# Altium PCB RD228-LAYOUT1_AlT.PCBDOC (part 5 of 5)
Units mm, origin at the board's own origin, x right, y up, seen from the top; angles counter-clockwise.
Board outline 130 x 73 mm, 4 copper layers (TOP, Mid-Layer 1, Mid-Layer 2, BOTTOM), stack 0.711 mm thick; 225 components, 171 nets, 818 pads, 538 vias.
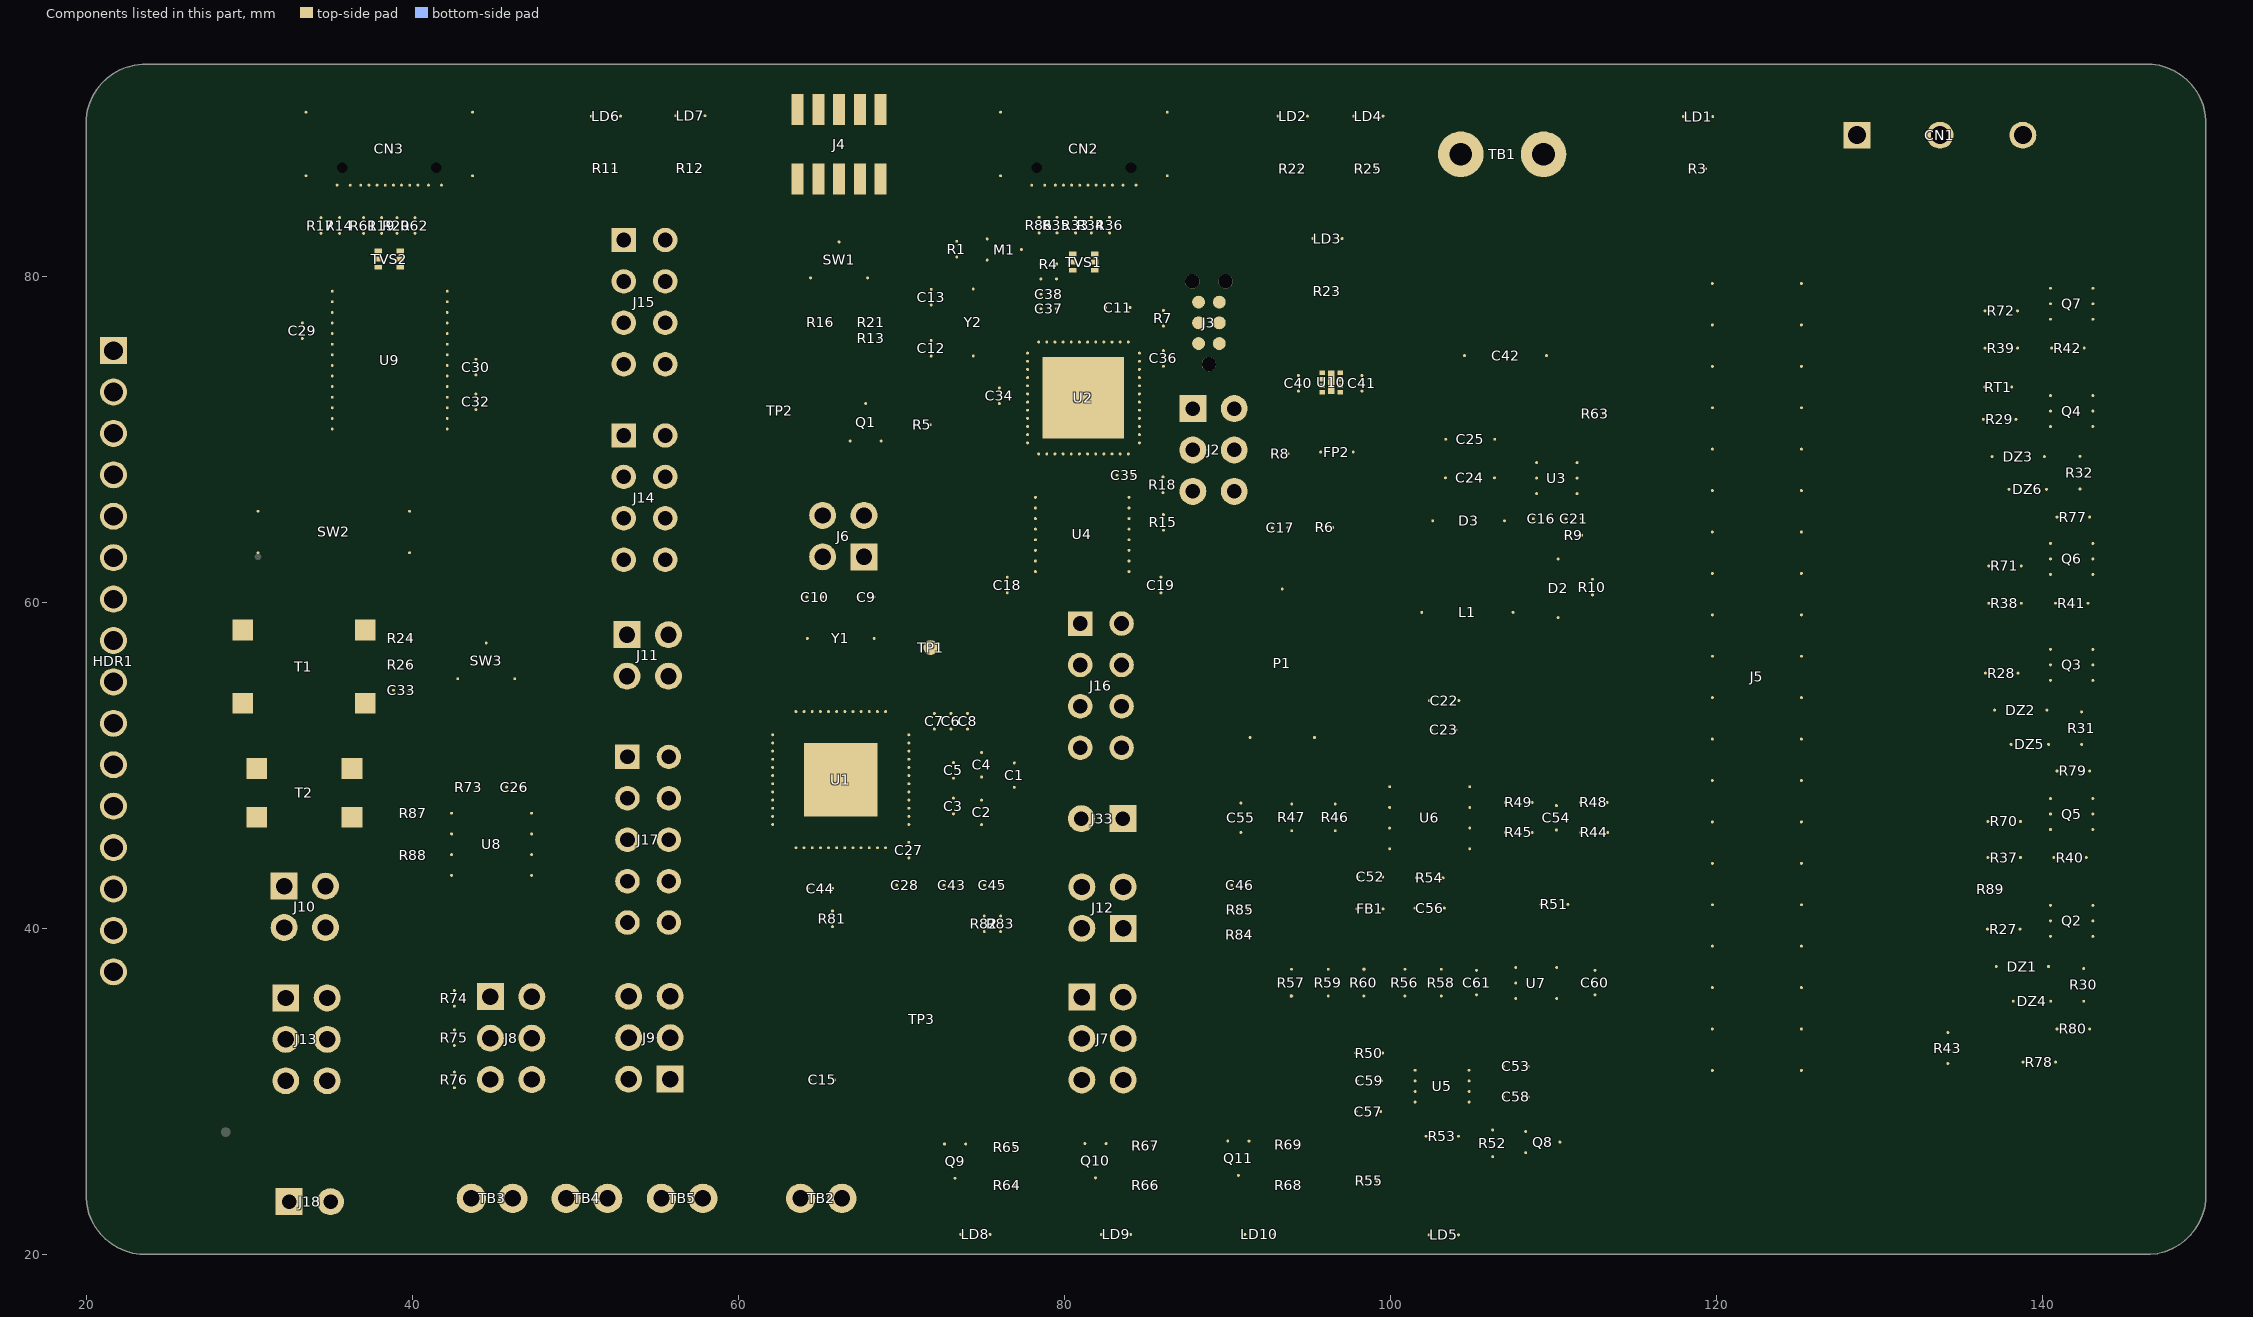
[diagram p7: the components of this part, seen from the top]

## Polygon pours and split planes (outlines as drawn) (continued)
no net on Top Overlay "TOPOVERLAY338" (solid, pour order 0): 165 vertices, not listed, extent 57.634,54.969 58.568,55.978
no net on Top Overlay "TOPOVERLAY337" (solid, pour order 0): 57.316,54.985 57.316,55.961 57.446,55.961 57.446,54.985
no net on Top Overlay "TOPOVERLAY336" (solid, pour order 0): 48 vertices, not listed, extent 58.498,81.756 58.857,82.737
no net on Top Overlay "TOPOVERLAY335" (solid, pour order 0): 165 vertices, not listed, extent 57.354,81.74 58.289,82.75
no net on Top Overlay "TOPOVERLAY334" (solid, pour order 0): 57.037,81.756 57.037,82.733 57.167,82.733 57.167,81.756
no net on Top Overlay "TOPOVERLAY333" (solid, pour order 0): 58.791,79.216 58.791,79.45 58.367,79.45 58.367,79.559 58.813,80.193 58.911,80.193 58.911,79.559 59.042,79.559 59.042,79.45 58.911,79.45 58.911,79.216
no net on Top Overlay "TOPOVERLAY332" (solid, pour order 0): 165 vertices, not listed, extent 57.354,79.2 58.289,80.21
no net on Top Overlay "TOPOVERLAY331" (solid, pour order 0): 57.037,79.216 57.037,80.193 57.167,80.193 57.167,79.216
no net on Top Overlay "TOPOVERLAY330" (solid, pour order 0): 165 vertices, not listed, extent 57.354,76.66 58.289,77.67
no net on Top Overlay "TOPOVERLAY329" (solid, pour order 0): 203 vertices, not listed, extent 58.405,76.66 59.048,77.657
no net on Top Overlay "TOPOVERLAY328" (solid, pour order 0): 57.037,76.676 57.037,77.653 57.167,77.653 57.167,76.676
no net on Top Overlay "TOPOVERLAY327" (solid, pour order 0): 48 vertices, not listed, extent 59.256,74.035 59.616,75.015
no net on Top Overlay "TOPOVERLAY326" (solid, pour order 0): 48 vertices, not listed, extent 58.498,74.035 58.857,75.015
no net on Top Overlay "TOPOVERLAY325" (solid, pour order 0): 165 vertices, not listed, extent 57.354,74.019 58.289,75.028
no net on Top Overlay "TOPOVERLAY324" (solid, pour order 0): 57.037,74.035 57.037,75.011 57.167,75.011 57.167,74.035
no net on Top Overlay "TOPOVERLAY323" (solid, pour order 0): 57.037,69.768 57.037,70.744 57.167,70.744 57.167,69.768
no net on Top Overlay "TOPOVERLAY322" (solid, pour order 0): 165 vertices, not listed, extent 57.354,69.751 58.289,70.761
no net on Top Overlay "TOPOVERLAY321" (solid, pour order 0): 152 vertices, not listed, extent 58.406,69.751 59.042,70.748
no net on Top Overlay "TOPOVERLAY320" (solid, pour order 0): 312 vertices, not listed, extent 58.407,67.186 59.046,68.182
no net on Top Overlay "TOPOVERLAY319" (solid, pour order 0): 165 vertices, not listed, extent 57.354,67.186 58.289,68.196
no net on Top Overlay "TOPOVERLAY318" (solid, pour order 0): 57.037,67.202 57.037,68.179 57.167,68.179 57.167,67.202
no net on Top Overlay "TOPOVERLAY317" (solid, pour order 0): 93 vertices, not listed, extent 58.414,64.688 59.046,65.652
no net on Top Overlay "TOPOVERLAY316" (solid, pour order 0): 165 vertices, not listed, extent 57.354,64.671 58.289,65.681
no net on Top Overlay "TOPOVERLAY315" (solid, pour order 0): 57.037,64.688 57.037,65.664 57.167,65.664 57.167,64.688
no net on Top Overlay "TOPOVERLAY314" (solid, pour order 0): 48 vertices, not listed, extent 58.498,62.148 58.857,63.128
no net on Top Overlay "TOPOVERLAY313" (solid, pour order 0): 165 vertices, not listed, extent 57.354,62.131 58.289,63.141
no net on Top Overlay "TOPOVERLAY312" (solid, pour order 0): 152 vertices, not listed, extent 59.164,62.131 59.8,63.128
no net on Top Overlay "TOPOVERLAY311" (solid, pour order 0): 57.037,62.148 57.037,63.124 57.167,63.124 57.167,62.148
no net on Top Overlay "TOPOVERLAY310" (solid, pour order 0): 295 vertices, not listed, extent 56.681,26.927 57.584,27.937
no net on Top Overlay "TOPOVERLAY309" (solid, pour order 0): 57.774,26.943 57.774,27.92 57.906,27.92 58.42,27.153 58.42,27.92 58.544,27.92 58.544,26.943 58.41,26.943 57.898,27.709 57.898,26.943
no net on Top Overlay "TOPOVERLAY308" (solid, pour order 0): 100 vertices, not listed, extent 58.76,26.943 59.568,27.92
no net on Top Overlay "TOPOVERLAY307" (solid, pour order 0): 50 vertices, not listed, extent 57.007,87.649 57.902,88.626
no net on Top Overlay "TOPOVERLAY306" (solid, pour order 0): 56.521,87.649 56.521,88.51 56.199,88.51 56.199,88.626 56.973,88.626 56.973,88.51 56.65,88.51 56.65,87.649
no net on Top Overlay "TOPOVERLAY305" (solid, pour order 0): 216 vertices, not listed, extent 57.596,85.135 58.241,86.115
no net on Top Overlay "TOPOVERLAY304" (solid, pour order 0): 119 vertices, not listed, extent 55.919,85.135 56.778,86.111
no net on Top Overlay "TOPOVERLAY303" (solid, pour order 0): 48 vertices, not listed, extent 56.945,85.135 57.304,86.115
no net on Top Overlay "TOPOVERLAY302" (solid, pour order 0): 53.975,27.101 53.975,27.369 53.71,27.369 53.71,27.48 53.975,27.48 53.975,27.746 54.089,27.746 54.089,27.48 54.355,27.48 54.355,27.369 54.089,27.369 54.089,27.101
no net on Top Overlay "TOPOVERLAY301" (solid, pour order 0): 31 vertices, not listed, extent 55.194,26.943 56.087,27.92
no net on Top Overlay "TOPOVERLAY300" (solid, pour order 0): 200 vertices, not listed, extent 54.486,26.927 55.134,27.907
no net on Top Overlay "TOPOVERLAY299" (solid, pour order 0): 110 vertices, not listed, extent 53.484,59.591 54.021,60.584
no net on Top Overlay "TOPOVERLAY298" (solid, pour order 0): 48 vertices, not listed, extent 55.034,59.608 55.393,60.588
no net on Top Overlay "TOPOVERLAY297" (solid, pour order 0): 48 vertices, not listed, extent 54.275,59.608 54.635,60.588
no net on Top Overlay "TOPOVERLAY296" (solid, pour order 0): 110 vertices, not listed, extent 53.408,51.895 53.945,52.888
no net on Top Overlay "TOPOVERLAY295" (solid, pour order 0): 93 vertices, not listed, extent 54.874,51.911 55.505,52.875
no net on Top Overlay "TOPOVERLAY294" (solid, pour order 0): 48 vertices, not listed, extent 54.199,51.911 54.558,52.892
no net on Top Overlay "TOPOVERLAY293" (solid, pour order 0): 110 vertices, not listed, extent 53.281,37.519 53.818,38.511
no net on Top Overlay "TOPOVERLAY292" (solid, pour order 0): 241 vertices, not listed, extent 53.98,37.519 54.622,38.515
no net on Top Overlay "TOPOVERLAY291" (solid, pour order 0): 110 vertices, not listed, extent 53.179,83.594 53.716,84.587
no net on Top Overlay "TOPOVERLAY290" (solid, pour order 0): 200 vertices, not listed, extent 54.636,83.594 55.284,84.575
no net on Top Overlay "TOPOVERLAY289" (solid, pour order 0): 48 vertices, not listed, extent 53.971,83.611 54.33,84.591
no net on Top Overlay "TOPOVERLAY288" (solid, pour order 0): 110 vertices, not listed, extent 53.154,71.606 53.691,72.598
no net on Top Overlay "TOPOVERLAY287" (solid, pour order 0): 48 vertices, not listed, extent 53.945,71.622 54.304,72.602
no net on Top Overlay "TOPOVERLAY286" (solid, pour order 0): 54.996,71.622 54.996,71.855 54.572,71.855 54.572,71.965 55.018,72.598 55.116,72.598 55.116,71.965 55.247,71.965 55.247,71.855 55.116,71.855 55.116,71.622
no net on Top Overlay "TOPOVERLAY285" (solid, pour order 0): 50 vertices, not listed, extent 51.864,87.598 52.759,88.575
no net on Top Overlay "TOPOVERLAY284" (solid, pour order 0): 119 vertices, not listed, extent 50.981,87.598 51.839,88.575
no net on Top Overlay "TOPOVERLAY283" (solid, pour order 0): 48 vertices, not listed, extent 52.598,85.084 52.957,86.064
no net on Top Overlay "TOPOVERLAY282" (solid, pour order 0): 119 vertices, not listed, extent 50.814,85.084 51.672,86.06
no net on Top Overlay "TOPOVERLAY281" (solid, pour order 0): 48 vertices, not listed, extent 51.84,85.084 52.199,86.064
no net on Top Overlay "TOPOVERLAY280" (solid, pour order 0): 50.763,26.943 50.763,27.92 50.893,27.92 50.893,27.519 51.4,27.519 51.4,27.92 51.529,27.92 51.529,26.943 51.4,26.943 51.4,27.403 50.893,27.403 50.893,26.943
no net on Top Overlay "TOPOVERLAY279" (solid, pour order 0): 51.681,27.237 51.681,27.358 52.05,27.358 52.05,27.237
no net on Top Overlay "TOPOVERLAY278" (solid, pour order 0): 96 vertices, not listed, extent 52.109,26.943 53.366,27.92
no net on Top Overlay "TOPOVERLAY277" (solid, pour order 0): 371 vertices, not listed, extent 50.864,42.37 51.64,43.38
no net on Top Overlay "TOPOVERLAY276" (solid, pour order 0): 274 vertices, not listed, extent 49.885,42.37 50.747,43.38
no net on Top Overlay "TOPOVERLAY275" (solid, pour order 0): 371 vertices, not listed, extent 49.55,47.45 50.327,48.46
no net on Top Overlay "TOPOVERLAY274" (solid, pour order 0): 100 vertices, not listed, extent 50.503,47.466 51.311,48.443
no net on Top Overlay "TOPOVERLAY273" (solid, pour order 0): 51.511,47.466 51.511,48.443 51.64,48.443 51.64,47.466
no net on Top Overlay "TOPOVERLAY272" (solid, pour order 0): 96 vertices, not listed, extent 49.517,39.846 50.773,40.823
no net on Top Overlay "TOPOVERLAY271" (solid, pour order 0): 75 vertices, not listed, extent 50.893,39.846 51.639,40.823
no net on Top Overlay "TOPOVERLAY270" (solid, pour order 0): 49.315,30.271 49.315,31.247 49.445,31.247 49.445,30.846 49.952,30.846 49.952,31.247 50.081,31.247 50.081,30.271 49.952,30.271 49.952,30.731 49.445,30.731 49.445,30.271
no net on Top Overlay "TOPOVERLAY269" (solid, pour order 0): 50.234,30.564 50.234,30.685 50.602,30.685 50.602,30.564
no net on Top Overlay "TOPOVERLAY268" (solid, pour order 0): 148 vertices, not listed, extent 50.753,30.254 51.521,31.247
no net on Top Overlay "TOPOVERLAY267" (solid, pour order 0): 49.188,32.633 49.188,33.609 49.318,33.609 49.318,33.208 49.825,33.208 49.825,33.609 49.954,33.609 49.954,32.633 49.825,32.633 49.825,33.093 49.318,33.093 49.318,32.633
no net on Top Overlay "TOPOVERLAY266" (solid, pour order 0): 50.107,32.926 50.107,33.047 50.475,33.047 50.475,32.926
no net on Top Overlay "TOPOVERLAY265" (solid, pour order 0): 31 vertices, not listed, extent 50.524,32.633 51.417,33.609
no net on Top Overlay "TOPOVERLAY264" (solid, pour order 0): 48.985,35.249 48.985,36.225 49.115,36.225 49.115,35.824 49.622,35.824 49.622,36.225 49.751,36.225 49.751,35.249 49.622,35.249 49.622,35.709 49.115,35.709 49.115,35.249
no net on Top Overlay "TOPOVERLAY263" (solid, pour order 0): 49.903,35.542 49.903,35.663 50.272,35.663 50.272,35.542
no net on Top Overlay "TOPOVERLAY262" (solid, pour order 0): 96 vertices, not listed, extent 50.331,35.249 51.588,36.225
no net on Top Overlay "TOPOVERLAY261" (solid, pour order 0): 371 vertices, not listed, extent 48.901,44.91 49.677,45.92
no net on Top Overlay "TOPOVERLAY260" (solid, pour order 0): 274 vertices, not listed, extent 49.816,44.91 50.679,45.92
no net on Top Overlay "TOPOVERLAY259" (solid, pour order 0): 50.833,44.926 50.833,45.903 50.963,45.903 50.963,45.419 51.447,45.903 51.622,45.903 51.212,45.507 51.64,44.926 51.469,44.926 51.122,45.419 50.963,45.265 50.963,44.926
no net on Top Overlay "TOPOVERLAY258" (solid, pour order 0): 371 vertices, not listed, extent 48.807,49.99 49.584,51
no net on Top Overlay "TOPOVERLAY257" (solid, pour order 0): 165 vertices, not listed, extent 50.706,49.99 51.64,51
no net on Top Overlay "TOPOVERLAY256" (solid, pour order 0): 100 vertices, not listed, extent 49.76,50.006 50.568,50.983
no net on Top Overlay "TOPOVERLAY255" (solid, pour order 0): 47.995,26.918 47.995,27.894 48.124,27.894 48.124,27.493 48.631,27.493 48.631,27.894 48.76,27.894 48.76,26.918 48.631,26.918 48.631,27.378 48.124,27.378 48.124,26.918
no net on Top Overlay "TOPOVERLAY254" (solid, pour order 0): 48.913,27.211 48.913,27.332 49.282,27.332 49.282,27.211
no net on Top Overlay "TOPOVERLAY253" (solid, pour order 0): 31 vertices, not listed, extent 49.33,26.918 50.224,27.894
no net on Top Overlay "TOPOVERLAY252" (solid, pour order 0): 119 vertices, not listed, extent 49.235,56.306 50.093,57.282
no net on Top Overlay "TOPOVERLAY251" (solid, pour order 0): 100 vertices, not listed, extent 47.868,56.306 48.675,57.282
no net on Top Overlay "TOPOVERLAY250" (solid, pour order 0): 48.875,56.306 48.875,57.282 49.005,57.282 49.005,56.306
no net on Top Overlay "TOPOVERLAY249" (solid, pour order 0): 50 vertices, not listed, extent 48.269,77.464 49.164,78.44
no net on Top Overlay "TOPOVERLAY248" (solid, pour order 0): 47.783,77.464 47.783,78.325 47.461,78.325 47.461,78.44 48.236,78.44 48.236,78.325 47.913,78.325 47.913,77.464
no net on Top Overlay "TOPOVERLAY247" (solid, pour order 0): 50 vertices, not listed, extent 47.989,65.373 48.884,66.35
no net on Top Overlay "TOPOVERLAY246" (solid, pour order 0): 119 vertices, not listed, extent 47.106,65.373 47.964,66.35
no net on Top Overlay "TOPOVERLAY245" (solid, pour order 0): 148 vertices, not listed, extent 46.742,78.845 47.51,79.837
no net on Top Overlay "TOPOVERLAY244" (solid, pour order 0): 47.618,78.861 47.991,79.837 48.132,79.837 48.531,78.861 48.384,78.861 48.271,79.156 47.861,79.156 47.754,78.861
no net on Top Overlay "TOPOVERLAY243" (solid, pour order 0): 119 vertices, not listed, extent 48.636,78.861 49.495,79.837
no net on Top Overlay "TOPOVERLAY242" (solid, pour order 0): 49.867,78.861 49.867,79.722 49.545,79.722 49.545,79.837 50.319,79.837 50.319,79.722 49.996,79.722 49.996,78.861
no net on Top Overlay "TOPOVERLAY241" (solid, pour order 0): 148 vertices, not listed, extent 46.386,66.754 47.154,67.747
no net on Top Overlay "TOPOVERLAY240" (solid, pour order 0): 47.263,66.77 47.636,67.747 47.776,67.747 48.175,66.77 48.028,66.77 47.915,67.066 47.505,67.066 47.399,66.77
no net on Top Overlay "TOPOVERLAY239" (solid, pour order 0): 119 vertices, not listed, extent 48.281,66.77 49.139,67.747
no net on Top Overlay "TOPOVERLAY238" (solid, pour order 0): 49.511,66.77 49.511,67.632 49.189,67.632 49.189,67.747 49.964,67.747 49.964,67.632 49.641,67.632 49.641,66.77
no net on Top Overlay "TOPOVERLAY237" (solid, pour order 0): 110 vertices, not listed, extent 45.376,37.57 45.913,38.562
no net on Top Overlay "TOPOVERLAY236" (solid, pour order 0): 203 vertices, not listed, extent 46.074,37.57 46.717,38.566
no net on Top Overlay "TOPOVERLAY235" (solid, pour order 0): 274 vertices, not listed, extent 45.15,87.551 46.013,88.56
no net on Top Overlay "TOPOVERLAY234" (solid, pour order 0): 312 vertices, not listed, extent 47.109,87.551 47.748,88.547
no net on Top Overlay "TOPOVERLAY233" (solid, pour order 0): 46.171,87.567 46.171,88.543 46.303,88.543 46.817,87.776 46.817,88.543 46.941,88.543 46.941,87.567 46.807,87.567 46.295,88.333 46.295,87.567
no net on Top Overlay "TOPOVERLAY232" (solid, pour order 0): 220 vertices, not listed, extent 46.826,49.228 47.471,50.225
no net on Top Overlay "TOPOVERLAY231" (solid, pour order 0): 274 vertices, not listed, extent 45.099,49.228 45.962,50.238
no net on Top Overlay "TOPOVERLAY230" (solid, pour order 0): 216 vertices, not listed, extent 46.057,49.244 46.702,50.225
no net on Top Overlay "TOPOVERLAY229" (solid, pour order 0): 45.074,26.918 45.074,27.894 45.203,27.894 45.203,27.493 45.71,27.493 45.71,27.894 45.839,27.894 45.839,26.918 45.71,26.918 45.71,27.378 45.203,27.378 45.203,26.918
no net on Top Overlay "TOPOVERLAY228" (solid, pour order 0): 45.992,27.211 45.992,27.332 46.361,27.332 46.361,27.211
no net on Top Overlay "TOPOVERLAY227" (solid, pour order 0): 148 vertices, not listed, extent 46.511,26.902 47.279,27.894
no net on Top Overlay "TOPOVERLAY226" (solid, pour order 0): 274 vertices, not listed, extent 44.489,71.783 45.352,72.793
no net on Top Overlay "TOPOVERLAY225" (solid, pour order 0): 312 vertices, not listed, extent 45.464,71.783 46.103,72.78
no net on Top Overlay "TOPOVERLAY224" (solid, pour order 0): 216 vertices, not listed, extent 46.206,71.8 46.851,72.78
no net on Top Overlay "TOPOVERLAY223" (solid, pour order 0): 274 vertices, not listed, extent 44.464,73.917 45.327,74.927
no net on Top Overlay "TOPOVERLAY222" (solid, pour order 0): 312 vertices, not listed, extent 45.438,73.917 46.078,74.913
no net on Top Overlay "TOPOVERLAY221" (solid, pour order 0): 151 vertices, not listed, extent 46.196,73.917 46.832,74.913
no net on Top Overlay "TOPOVERLAY220" (solid, pour order 0): 148 vertices, not listed, extent 44.235,41.329 45.003,42.321
no net on Top Overlay "TOPOVERLAY219" (solid, pour order 0): 203 vertices, not listed, extent 45.168,41.329 45.811,42.325
no net on Top Overlay "TOPOVERLAY218" (solid, pour order 0): 371 vertices, not listed, extent 43.092,58.474 43.869,59.484
no net on Top Overlay "TOPOVERLAY217" (solid, pour order 0): 312 vertices, not listed, extent 45.285,58.474 45.924,59.47
no net on Top Overlay "TOPOVERLAY216" (solid, pour order 0): 96 vertices, not listed, extent 43.956,58.49 45.213,59.466
no net on Top Overlay "TOPOVERLAY215" (solid, pour order 0): 312 vertices, not listed, extent 43.947,49.228 44.586,50.225
no net on Top Overlay "TOPOVERLAY214" (solid, pour order 0): 119 vertices, not listed, extent 42.254,49.244 43.112,50.221
no net on Top Overlay "TOPOVERLAY213" (solid, pour order 0): 94 vertices, not listed, extent 43.196,49.244 43.828,50.208
no net on Top Overlay "TOPOVERLAY212" (solid, pour order 0): 42.393,27.076 42.393,27.344 42.127,27.344 42.127,27.455 42.393,27.455 42.393,27.721 42.506,27.721 42.506,27.455 42.772,27.455 42.772,27.344 42.506,27.344 42.506,27.076
no net on Top Overlay "TOPOVERLAY211" (solid, pour order 0): 31 vertices, not listed, extent 43.611,26.918 44.505,27.894
no net on Top Overlay "TOPOVERLAY210" (solid, pour order 0): 200 vertices, not listed, extent 42.904,26.902 43.551,27.882
no net on Top Overlay "TOPOVERLAY209" (solid, pour order 0): 42 vertices, not listed, extent 41.162,65.119 42.096,66.096
no net on Top Overlay "TOPOVERLAY208" (solid, pour order 0): 151 vertices, not listed, extent 43.239,65.103 43.875,66.1
no net on Top Overlay "TOPOVERLAY207" (solid, pour order 0): 100 vertices, not listed, extent 42.302,65.119 43.11,66.096
no net on Top Overlay "TOPOVERLAY206" (solid, pour order 0): 42 vertices, not listed, extent 41.162,62.554 42.096,63.53
no net on Top Overlay "TOPOVERLAY205" (solid, pour order 0): 100 vertices, not listed, extent 42.302,62.554 43.11,63.53
no net on Top Overlay "TOPOVERLAY204" (solid, pour order 0): 48 vertices, not listed, extent 43.331,62.554 43.69,63.534
no net on Top Overlay "TOPOVERLAY203" (solid, pour order 0): 220 vertices, not listed, extent 41.684,82.604 42.329,83.6
no net on Top Overlay "TOPOVERLAY202" (solid, pour order 0): 119 vertices, not listed, extent 40.756,82.62 41.614,83.596
no net on Top Overlay "TOPOVERLAY201" (solid, pour order 0): 216 vertices, not listed, extent 42.432,82.62 43.077,83.6
no net on Top Overlay "TOPOVERLAY200" (solid, pour order 0): 30 vertices, not listed, extent 40.537,80.563 41.43,81.539
no net on Top Overlay "TOPOVERLAY199" (solid, pour order 0): 371 vertices, not listed, extent 41.502,80.546 42.279,81.556
no net on Top Overlay "TOPOVERLAY198" (solid, pour order 0): 40.051,80.563 40.051,81.424 39.729,81.424 39.729,81.539 40.503,81.539 40.503,81.424 40.18,81.424 40.18,80.563
no net on Top Overlay "TOPOVERLAY197" (solid, pour order 0): 216 vertices, not listed, extent 42.391,80.563 43.036,81.543
no net on Top Overlay "TOPOVERLAY196" (solid, pour order 0): 41.765,35.147 41.765,35.381 41.341,35.381 41.341,35.49 41.787,36.124 41.885,36.124 41.885,35.49 42.017,35.49 42.017,35.381 41.885,35.381 41.885,35.147
no net on Top Overlay "TOPOVERLAY195" (solid, pour order 0): 119 vertices, not listed, extent 39.689,35.147 40.547,36.124
no net on Top Overlay "TOPOVERLAY194" (solid, pour order 0): 94 vertices, not listed, extent 40.631,35.147 41.262,36.111
no net on Top Overlay "TOPOVERLAY193" (solid, pour order 0): 220 vertices, not listed, extent 41.354,30.178 41.999,31.175
no net on Top Overlay "TOPOVERLAY192" (solid, pour order 0): 119 vertices, not listed, extent 39.667,30.194 40.526,31.171
no net on Top Overlay "TOPOVERLAY191" (solid, pour order 0): 94 vertices, not listed, extent 40.61,30.194 41.241,31.158
no net on Top Overlay "TOPOVERLAY190" (solid, pour order 0): 200 vertices, not listed, extent 41.304,32.769 41.952,33.749
no net on Top Overlay "TOPOVERLAY189" (solid, pour order 0): 119 vertices, not listed, extent 39.613,32.785 40.471,33.762
no net on Top Overlay "TOPOVERLAY188" (solid, pour order 0): 94 vertices, not listed, extent 40.555,32.785 41.186,33.749
no net on Top Overlay "TOPOVERLAY187" (solid, pour order 0): 203 vertices, not listed, extent 39.758,47.577 40.401,48.574
no net on Top Overlay "TOPOVERLAY186" (solid, pour order 0): 119 vertices, not listed, extent 38.825,47.593 39.683,48.57
no net on Top Overlay "TOPOVERLAY185" (solid, pour order 0): 94 vertices, not listed, extent 40.525,47.593 41.157,48.557
no net on Top Overlay "TOPOVERLAY184" (solid, pour order 0): 203 vertices, not listed, extent 39.758,45.012 40.401,46.008
no net on Top Overlay "TOPOVERLAY183" (solid, pour order 0): 203 vertices, not listed, extent 40.516,45.012 41.159,46.008
no net on Top Overlay "TOPOVERLAY182" (solid, pour order 0): 119 vertices, not listed, extent 38.825,45.028 39.683,46.004
no net on Top Overlay "TOPOVERLAY181" (solid, pour order 0): 40.216,58.439 40.216,58.673 39.792,58.673 39.792,58.782 40.238,59.416 40.336,59.416 40.336,58.782 40.467,58.782 40.467,58.673 40.336,58.673 40.336,58.439
no net on Top Overlay "TOPOVERLAY180" (solid, pour order 0): 119 vertices, not listed, extent 38.139,58.439 38.998,59.416
no net on Top Overlay "TOPOVERLAY179" (solid, pour order 0): 216 vertices, not listed, extent 39.058,58.439 39.703,59.419
no net on Top Overlay "TOPOVERLAY178" (solid, pour order 0): 274 vertices, not listed, extent 38.089,53.038 38.951,54.048
no net on Top Overlay "TOPOVERLAY177" (solid, pour order 0): 312 vertices, not listed, extent 39.821,53.038 40.46,54.035
no net on Top Overlay "TOPOVERLAY176" (solid, pour order 0): 312 vertices, not listed, extent 39.063,53.038 39.702,54.035
no net on Top Overlay "TOPOVERLAY175" (solid, pour order 0): 100 vertices, not listed, extent 21.035,77.134 21.843,78.11
no net on Top Overlay "TOPOVERLAY174" (solid, pour order 0): 20.055,77.134 20.055,78.11 20.184,78.11 20.184,77.709 20.691,77.709 20.691,78.11 20.82,78.11 20.82,77.134 20.691,77.134 20.691,77.594 20.184,77.594 20.184,77.134
no net on Top Overlay "TOPOVERLAY173" (solid, pour order 0): 48 vertices, not listed, extent 23.048,77.134 23.407,78.114
no net on Top Overlay "TOPOVERLAY172" (solid, pour order 0): 119 vertices, not listed, extent 22.023,77.134 22.881,78.11
no net on Top Overlay "TOPOVERLAY171" (solid, pour order 0): 94 vertices, not listed, extent 37.967,35.224 38.599,36.188
no net on Top Overlay "TOPOVERLAY170" (solid, pour order 0): 165 vertices, not listed, extent 36.907,35.207 37.842,36.217
no net on Top Overlay "TOPOVERLAY169" (solid, pour order 0): 36.59,35.224 36.59,36.2 36.72,36.2 36.72,35.224
no net on Top Overlay "TOPOVERLAY168" (solid, pour order 0): 165 vertices, not listed, extent 36.907,32.617 37.842,33.626
no net on Top Overlay "TOPOVERLAY167" (solid, pour order 0): 203 vertices, not listed, extent 37.958,32.617 38.601,33.613
no net on Top Overlay "TOPOVERLAY166" (solid, pour order 0): 36.59,32.633 36.59,33.609 36.72,33.609 36.72,32.633
no net on Top Overlay "TOPOVERLAY165" (solid, pour order 0): 241 vertices, not listed, extent 37.959,30.127 38.601,31.124
no net on Top Overlay "TOPOVERLAY164" (solid, pour order 0): 165 vertices, not listed, extent 36.907,30.127 37.842,31.137
no net on Top Overlay "TOPOVERLAY163" (solid, pour order 0): 36.59,30.144 36.59,31.12 36.72,31.12 36.72,30.144
no net on Top Overlay "TOPOVERLAY162" (solid, pour order 0): 241 vertices, not listed, extent 37.781,39.652 38.423,40.649
no net on Top Overlay "TOPOVERLAY161" (solid, pour order 0): 165 vertices, not listed, extent 36.729,39.652 37.664,40.662
no net on Top Overlay "TOPOVERLAY160" (solid, pour order 0): 36.412,39.669 36.412,40.645 36.542,40.645 36.542,39.669
no net on Top Overlay "TOPOVERLAY159" (solid, pour order 0): 94 vertices, not listed, extent 37.757,42.056 38.388,43.02
no net on Top Overlay "TOPOVERLAY158" (solid, pour order 0): 165 vertices, not listed, extent 36.696,42.04 37.631,43.05
no net on Top Overlay "TOPOVERLAY157" (solid, pour order 0): 36.379,42.056 36.379,43.033 36.509,43.033 36.509,42.056
no net on Top Overlay "TOPOVERLAY156" (solid, pour order 0): 148 vertices, not listed, extent 34.38,79.988 35.148,80.98
no net on Top Overlay "TOPOVERLAY155" (solid, pour order 0): 241 vertices, not listed, extent 35.314,79.988 35.956,80.984
no net on Top Overlay "TOPOVERLAY154" (solid, pour order 0): 295 vertices, not listed, extent 33.974,24.92 34.877,25.93
no net on Top Overlay "TOPOVERLAY153" (solid, pour order 0): 35.066,24.937 35.066,25.913 35.199,25.913 35.712,25.146 35.712,25.913 35.836,25.913 35.836,24.937 35.703,24.937 35.19,25.702 35.19,24.937
no net on Top Overlay "TOPOVERLAY152" (solid, pour order 0): 100 vertices, not listed, extent 36.052,24.937 36.86,25.913
no net on Top Overlay "TOPOVERLAY151" (solid, pour order 0): 371 vertices, not listed, extent 33.821,67.542 34.598,68.551
no net on Top Overlay "TOPOVERLAY150" (solid, pour order 0): 96 vertices, not listed, extent 34.685,67.558 35.942,68.534
no net on Top Overlay "TOPOVERLAY149" (solid, pour order 0): 216 vertices, not listed, extent 35.998,67.558 36.643,68.538
no net on Top Overlay "TOPOVERLAY148" (solid, pour order 0): 23.594,75.113 23.594,75.38 23.329,75.38 23.329,75.492 23.594,75.492 23.594,75.757 23.708,75.757 23.708,75.492 23.973,75.492 23.973,75.38 23.708,75.38 23.708,75.113
no net on Top Overlay "TOPOVERLAY147" (solid, pour order 0): 30 vertices, not listed, extent 24.813,74.954 25.706,75.931
no net on Top Overlay "TOPOVERLAY146" (solid, pour order 0): 200 vertices, not listed, extent 24.105,74.938 24.753,75.918
no net on Top Overlay "TOPOVERLAY145" (solid, pour order 0): 23.594,72.573 23.594,72.84 23.329,72.84 23.329,72.952 23.594,72.952 23.594,73.217 23.708,73.217 23.708,72.952 23.973,72.952 23.973,72.84 23.708,72.84 23.708,72.573
no net on Top Overlay "TOPOVERLAY144" (solid, pour order 0): 30 vertices, not listed, extent 24.813,72.414 25.706,73.391
no net on Top Overlay "TOPOVERLAY143" (solid, pour order 0): 200 vertices, not listed, extent 24.105,72.398 24.753,73.378
no net on Top Overlay "TOPOVERLAY142" (solid, pour order 0): 23.329,69.874 23.329,70.851 23.458,70.851 23.458,69.874
no net on Top Overlay "TOPOVERLAY141" (solid, pour order 0): 165 vertices, not listed, extent 23.646,69.858 24.58,70.868
no net on Top Overlay "TOPOVERLAY140" (solid, pour order 0): 151 vertices, not listed, extent 24.697,69.858 25.334,70.855
no net on Top Overlay "TOPOVERLAY139" (solid, pour order 0): 48 vertices, not listed, extent 24.79,67.334 25.149,68.315
no net on Top Overlay "TOPOVERLAY138" (solid, pour order 0): 165 vertices, not listed, extent 23.646,67.318 24.58,68.328
no net on Top Overlay "TOPOVERLAY137" (solid, pour order 0): 23.329,67.334 23.329,68.311 23.458,68.311 23.458,67.334
no net on Top Overlay "TOPOVERLAY136" (solid, pour order 0): 216 vertices, not listed, extent 24.682,64.794 25.327,65.775
no net on Top Overlay "TOPOVERLAY135" (solid, pour order 0): 165 vertices, not listed, extent 23.646,64.778 24.58,65.788
no net on Top Overlay "TOPOVERLAY134" (solid, pour order 0): 23.329,64.794 23.329,65.771 23.458,65.771 23.458,64.794
no net on Top Overlay "TOPOVERLAY133" (solid, pour order 0): 312 vertices, not listed, extent 24.698,62.238 25.337,63.235
no net on Top Overlay "TOPOVERLAY132" (solid, pour order 0): 165 vertices, not listed, extent 23.646,62.238 24.58,63.248
no net on Top Overlay "TOPOVERLAY131" (solid, pour order 0): 23.329,62.254 23.329,63.231 23.458,63.231 23.458,62.254
no net on Top Overlay "TOPOVERLAY130" (solid, pour order 0): 25.082,59.714 25.082,59.948 24.658,59.948 24.658,60.057 25.104,60.691 25.202,60.691 25.202,60.057 25.334,60.057 25.334,59.948 25.202,59.948 25.202,59.714
no net on Top Overlay "TOPOVERLAY129" (solid, pour order 0): 165 vertices, not listed, extent 23.646,59.698 24.58,60.708
no net on Top Overlay "TOPOVERLAY128" (solid, pour order 0): 23.329,59.714 23.329,60.691 23.458,60.691 23.458,59.714
no net on Top Overlay "TOPOVERLAY127" (solid, pour order 0): 200 vertices, not listed, extent 24.697,57.138 25.345,58.118
no net on Top Overlay "TOPOVERLAY126" (solid, pour order 0): 165 vertices, not listed, extent 23.646,57.138 24.58,58.147
no net on Top Overlay "TOPOVERLAY125" (solid, pour order 0): 23.329,57.154 23.329,58.13 23.458,58.13 23.458,57.154
no net on Top Overlay "TOPOVERLAY124" (solid, pour order 0): 220 vertices, not listed, extent 24.693,54.618 25.337,55.615
no net on Top Overlay "TOPOVERLAY123" (solid, pour order 0): 165 vertices, not listed, extent 23.646,54.618 24.58,55.628
no net on Top Overlay "TOPOVERLAY122" (solid, pour order 0): 23.329,54.634 23.329,55.611 23.458,55.611 23.458,54.634
no net on Top Overlay "TOPOVERLAY121" (solid, pour order 0): 94 vertices, not listed, extent 24.706,52.094 25.337,53.058
no net on Top Overlay "TOPOVERLAY120" (solid, pour order 0): 165 vertices, not listed, extent 23.646,52.078 24.58,53.088
no net on Top Overlay "TOPOVERLAY119" (solid, pour order 0): 23.329,52.094 23.329,53.071 23.458,53.071 23.458,52.094
no net on Top Overlay "TOPOVERLAY118" (solid, pour order 0): 165 vertices, not listed, extent 23.646,49.538 24.58,50.548
no net on Top Overlay "TOPOVERLAY117" (solid, pour order 0): 203 vertices, not listed, extent 24.696,49.538 25.339,50.535
no net on Top Overlay "TOPOVERLAY116" (solid, pour order 0): 23.329,49.554 23.329,50.531 23.458,50.531 23.458,49.554
no net on Top Overlay "TOPOVERLAY115" (solid, pour order 0): 241 vertices, not listed, extent 24.697,46.998 25.339,47.995
no net on Top Overlay "TOPOVERLAY114" (solid, pour order 0): 165 vertices, not listed, extent 23.646,46.998 24.58,48.008
no net on Top Overlay "TOPOVERLAY113" (solid, pour order 0): 23.329,47.014 23.329,47.991 23.458,47.991 23.458,47.014
no net on Top Overlay "TOPOVERLAY112" (solid, pour order 0): 48 vertices, not listed, extent 24.79,44.474 25.149,45.455
no net on Top Overlay "TOPOVERLAY111" (solid, pour order 0): 165 vertices, not listed, extent 23.646,44.458 24.58,45.468
no net on Top Overlay "TOPOVERLAY110" (solid, pour order 0): 151 vertices, not listed, extent 25.455,44.458 26.092,45.455
no net on Top Overlay "TOPOVERLAY109" (solid, pour order 0): 23.329,44.474 23.329,45.451 23.458,45.451 23.458,44.474
no net on Top Overlay "TOPOVERLAY108" (solid, pour order 0): 48 vertices, not listed, extent 25.548,41.934 25.907,42.915
no net on Top Overlay "TOPOVERLAY107" (solid, pour order 0): 48 vertices, not listed, extent 24.79,41.934 25.149,42.915
no net on Top Overlay "TOPOVERLAY106" (solid, pour order 0): 165 vertices, not listed, extent 23.646,41.918 24.58,42.928
no net on Top Overlay "TOPOVERLAY105" (solid, pour order 0): 23.329,41.934 23.329,42.911 23.458,42.911 23.458,41.934
no net on Top Overlay "TOPOVERLAY104" (solid, pour order 0): 295 vertices, not listed, extent 23.329,39.349 24.232,40.358
no net on Top Overlay "TOPOVERLAY103" (solid, pour order 0): 24.421,39.365 24.421,40.341 24.553,40.341 25.067,39.574 25.067,40.341 25.191,40.341 25.191,39.365 25.057,39.365 24.545,40.131 24.545,39.365
no net on Top Overlay "TOPOVERLAY102" (solid, pour order 0): 100 vertices, not listed, extent 25.407,39.365 26.215,40.341
no net on Top Overlay "TOPOVERLAY101" (solid, pour order 0): 295 vertices, not listed, extent 23.329,36.809 24.232,37.818
no net on Top Overlay "TOPOVERLAY100" (solid, pour order 0): 24.421,36.825 24.421,37.801 24.553,37.801 25.067,37.034 25.067,37.801 25.191,37.801 25.191,36.825 25.057,36.825 24.545,37.591 24.545,36.825
no net on Top Overlay "TOPOVERLAY99" (solid, pour order 0): 100 vertices, not listed, extent 25.407,36.825 26.215,37.801
no net on Top Overlay "TOPOVERLAY98" (solid, pour order 0): 312 vertices, not listed, extent 33.886,37.239 34.525,38.236
no net on Top Overlay "TOPOVERLAY97" (solid, pour order 0): 110 vertices, not listed, extent 32.427,37.239 32.965,38.232
no net on Top Overlay "TOPOVERLAY96" (solid, pour order 0): 48 vertices, not listed, extent 33.219,37.256 33.578,38.236
no net on Top Overlay "TOPOVERLAY95" (solid, pour order 0): 110 vertices, not listed, extent 32.326,44.097 32.863,45.09
no net on Top Overlay "TOPOVERLAY94" (solid, pour order 0): 152 vertices, not listed, extent 33.783,44.097 34.419,45.094
no net on Top Overlay "TOPOVERLAY93" (solid, pour order 0): 48 vertices, not listed, extent 33.117,44.114 33.476,45.094
no net on Top Overlay "TOPOVERLAY92" (solid, pour order 0): 371 vertices, not listed, extent 33.033,59.312 33.81,60.322
no net on Top Overlay "TOPOVERLAY91" (solid, pour order 0): 119 vertices, not listed, extent 32.094,59.328 32.952,60.305
no net on Top Overlay "TOPOVERLAY90" (solid, pour order 0): 34.235,59.328 34.235,60.189 33.913,60.189 33.913,60.305 34.687,60.305 34.687,60.189 34.364,60.189 34.364,59.328
no net on Top Overlay "TOPOVERLAY89" (solid, pour order 0): 165 vertices, not listed, extent 28.381,32.617 29.316,33.626
no net on Top Overlay "TOPOVERLAY88" (solid, pour order 0): 295 vertices, not listed, extent 27.327,32.617 28.23,33.626
no net on Top Overlay "TOPOVERLAY87" (solid, pour order 0): 117 vertices, not listed, extent 26.445,32.633 27.182,33.609
no net on Top Overlay "TOPOVERLAY86" (solid, pour order 0): 100 vertices, not listed, extent 25.465,32.633 26.273,33.609
no net on Top Overlay "TOPOVERLAY85" (solid, pour order 0): 94 vertices, not listed, extent 33.236,82.595 33.867,83.559
no net on Top Overlay "TOPOVERLAY84" (solid, pour order 0): 119 vertices, not listed, extent 31.535,82.595 32.394,83.571
no net on Top Overlay "TOPOVERLAY83" (solid, pour order 0): 48 vertices, not listed, extent 32.561,82.595 32.92,83.575
no net on Top Overlay "TOPOVERLAY82" (solid, pour order 0): 26.137,63.881 26.137,64.148 25.871,64.148 25.871,64.26 26.137,64.26 26.137,64.525 26.25,64.525 26.25,64.26 26.516,64.26 26.516,64.148 26.25,64.148 26.25,63.881
no net on Top Overlay "TOPOVERLAY81" (solid, pour order 0): 30 vertices, not listed, extent 27.355,63.722 28.249,64.699
no net on Top Overlay "TOPOVERLAY80" (solid, pour order 0): 200 vertices, not listed, extent 26.648,63.706 27.295,64.686
no net on Top Overlay "TOPOVERLAY79" (solid, pour order 0): 66 vertices, not listed, extent 32.618,51.327 33.003,52.051
no net on Top Overlay "TOPOVERLAY78" (solid, pour order 0): 33.363,51.311 33.646,52.321 33.742,52.321 33.46,51.311
no net on Top Overlay "TOPOVERLAY77" (solid, pour order 0): 114 vertices, not listed, extent 35.879,51.056 36.493,52.051
no net on Top Overlay "TOPOVERLAY76" (solid, pour order 0): 371 vertices, not listed, extent 33.804,51.311 34.581,52.321
no net on Top Overlay "TOPOVERLAY75" (solid, pour order 0): 371 vertices, not listed, extent 30.545,51.311 31.321,52.321
no net on Top Overlay "TOPOVERLAY74" (solid, pour order 0): 75 vertices, not listed, extent 34.675,51.318 35.021,52.282
no net on Top Overlay "TOPOVERLAY73" (solid, pour order 0): 75 vertices, not listed, extent 33.007,51.318 33.353,52.282
no net on Top Overlay "TOPOVERLAY72" (solid, pour order 0): 231 vertices, not listed, extent 31.821,51.311 32.472,52.051
no net on Top Overlay "TOPOVERLAY71" (solid, pour order 0): 124 vertices, not listed, extent 35.077,51.311 35.739,52.051
no net on Top Overlay "TOPOVERLAY70" (solid, pour order 0): 75 vertices, not listed, extent 31.415,51.318 31.761,52.282
no net on Top Overlay "TOPOVERLAY69" (solid, pour order 0): 274 vertices, not listed, extent 30.291,76.129 31.154,77.139
no net on Top Overlay "TOPOVERLAY68" (solid, pour order 0): 216 vertices, not listed, extent 31.249,76.146 31.894,77.126
no net on Top Overlay "TOPOVERLAY67" (solid, pour order 0): 241 vertices, not listed, extent 32.023,76.129 32.665,77.126
no net on Top Overlay "TOPOVERLAY66" (solid, pour order 0): 371 vertices, not listed, extent 28.151,40.872 28.927,41.881
no net on Top Overlay "TOPOVERLAY65" (solid, pour order 0): 371 vertices, not listed, extent 26.862,40.872 27.638,41.881
no net on Top Overlay "TOPOVERLAY64" (solid, pour order 0): 27.71,40.872 27.993,41.881 28.089,41.881 27.806,40.872
no net on Top Overlay "TOPOVERLAY63" (solid, pour order 0): 165 vertices, not listed, extent 32.522,24.92 33.456,25.93
no net on Top Overlay "TOPOVERLAY62" (solid, pour order 0): 295 vertices, not listed, extent 31.467,24.92 32.37,25.93
no net on Top Overlay "TOPOVERLAY61" (solid, pour order 0): 117 vertices, not listed, extent 30.585,24.937 31.322,25.913
no net on Top Overlay "TOPOVERLAY60" (solid, pour order 0): 100 vertices, not listed, extent 29.605,24.937 30.413,25.913
no net on Top Overlay "TOPOVERLAY59" (solid, pour order 0): 371 vertices, not listed, extent 30.065,87.478 30.969,88.655
no net on Top Overlay "TOPOVERLAY58" (solid, pour order 0): 117 vertices, not listed, extent 31.169,87.497 32.028,88.635
no net on Top Overlay "TOPOVERLAY57" (solid, pour order 0): 148 vertices, not listed, extent 28.97,87.478 29.865,88.635
no net on Top Overlay "TOPOVERLAY56" (solid, pour order 0): 203 vertices, not listed, extent 30.302,22.66 30.945,23.656
no net on Top Overlay "TOPOVERLAY55" (solid, pour order 0): 110 vertices, not listed, extent 28.846,22.66 29.383,23.652
no net on Top Overlay "TOPOVERLAY54" (solid, pour order 0): 48 vertices, not listed, extent 29.637,22.676 29.997,23.656
no net on Top Paste "TOPPASTE996" (solid, pour order 0): 64.433,49.487 64.433,50.987 65.933,50.987 65.933,49.487
no net on Top Paste "TOPPASTE995" (solid, pour order 0): 66.623,49.507 66.623,51.007 68.123,51.007 68.123,49.507
no net on Top Paste "TOPPASTE994" (solid, pour order 0): 66.623,47.267 66.623,48.767 68.123,48.767 68.123,47.267
no net on Top Paste "TOPPASTE993" (solid, pour order 0): 64.423,47.267 64.423,48.767 65.923,48.767 65.923,47.267
no net on Top Paste "TOPPASTE992" (solid, pour order 0): 82.118,70.276 82.118,71.576 83.418,71.576 83.418,70.276
no net on Top Paste "TOPPASTE991" (solid, pour order 0): 82.118,73.476 82.118,74.776 83.418,74.776 83.418,73.476
no net on Top Paste "TOPPASTE990" (solid, pour order 0): 78.918,73.476 78.918,74.776 80.218,74.776 80.218,73.476
no net on Top Paste "TOPPASTE989" (solid, pour order 0): 78.918,70.276 78.918,71.576 80.218,71.576 80.218,70.276
no net on Top Paste "TOPPASTE988" (solid, pour order 0): 80.518,70.276 80.518,71.576 81.818,71.576 81.818,70.276
no net on Top Paste "TOPPASTE987" (solid, pour order 0): 80.518,73.476 80.518,74.776 81.818,74.776 81.818,73.476
no net on Top Paste "TOPPASTE986" (solid, pour order 0): 82.118,71.876 82.118,73.176 83.418,73.176 83.418,71.876
no net on Top Paste "TOPPASTE985" (solid, pour order 0): 80.518,71.876 80.518,73.176 81.818,73.176 81.818,71.876
no net on Top Paste "TOPPASTE984" (solid, pour order 0): 78.918,71.876 78.918,73.176 80.218,73.176 80.218,71.876
no net on Bottom Overlay "BOTTOMOVERLAY1006" (solid, pour order 0): 96 vertices, not listed, extent 113.233,25.699 114.698,26.836
no net on Bottom Overlay "BOTTOMOVERLAY1005" (solid, pour order 0): 48 vertices, not listed, extent 108.031,25.699 108.449,26.841
no net on Bottom Overlay "BOTTOMOVERLAY1004" (solid, pour order 0): 114.844,25.699 114.844,26.836 114.995,26.836 114.995,26.369 115.586,26.369 115.586,26.836 115.736,26.836 115.736,25.699 115.586,25.699 115.586,26.235 114.995,26.235 114.995,25.699
no net on Bottom Overlay "BOTTOMOVERLAY1003" (solid, pour order 0): 48 vertices, not listed, extent 105.822,25.699 106.241,26.841
no net on Bottom Overlay "BOTTOMOVERLAY1002" (solid, pour order 0): 31 vertices, not listed, extent 109.518,25.699 110.56,26.836
no net on Bottom Overlay "BOTTOMOVERLAY1001" (solid, pour order 0): 107.436,25.699 107.436,25.857 107.595,25.857 107.595,25.699
no net on Bottom Overlay "BOTTOMOVERLAY1000" (solid, pour order 0): 152 vertices, not listed, extent 106.49,25.68 107.232,26.841
no net on Bottom Overlay "BOTTOMOVERLAY999" (solid, pour order 0): 109.203,25.699 109.203,25.857 109.362,25.857 109.362,25.699
no net on Bottom Overlay "BOTTOMOVERLAY998" (solid, pour order 0): 119 vertices, not listed, extent 111.648,25.699 112.649,26.836
no net on Bottom Overlay "BOTTOMOVERLAY997" (solid, pour order 0): 110.652,25.699 110.652,25.833 111.35,25.833 111.35,26.22 110.72,26.22 110.72,26.355 111.35,26.355 111.35,26.702 110.678,26.702 110.678,26.836 111.501,26.836 111.501,25.699

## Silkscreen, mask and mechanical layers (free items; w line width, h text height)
Top Overlay:
  drawing of 475 lines, arcs and shapes, not listed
